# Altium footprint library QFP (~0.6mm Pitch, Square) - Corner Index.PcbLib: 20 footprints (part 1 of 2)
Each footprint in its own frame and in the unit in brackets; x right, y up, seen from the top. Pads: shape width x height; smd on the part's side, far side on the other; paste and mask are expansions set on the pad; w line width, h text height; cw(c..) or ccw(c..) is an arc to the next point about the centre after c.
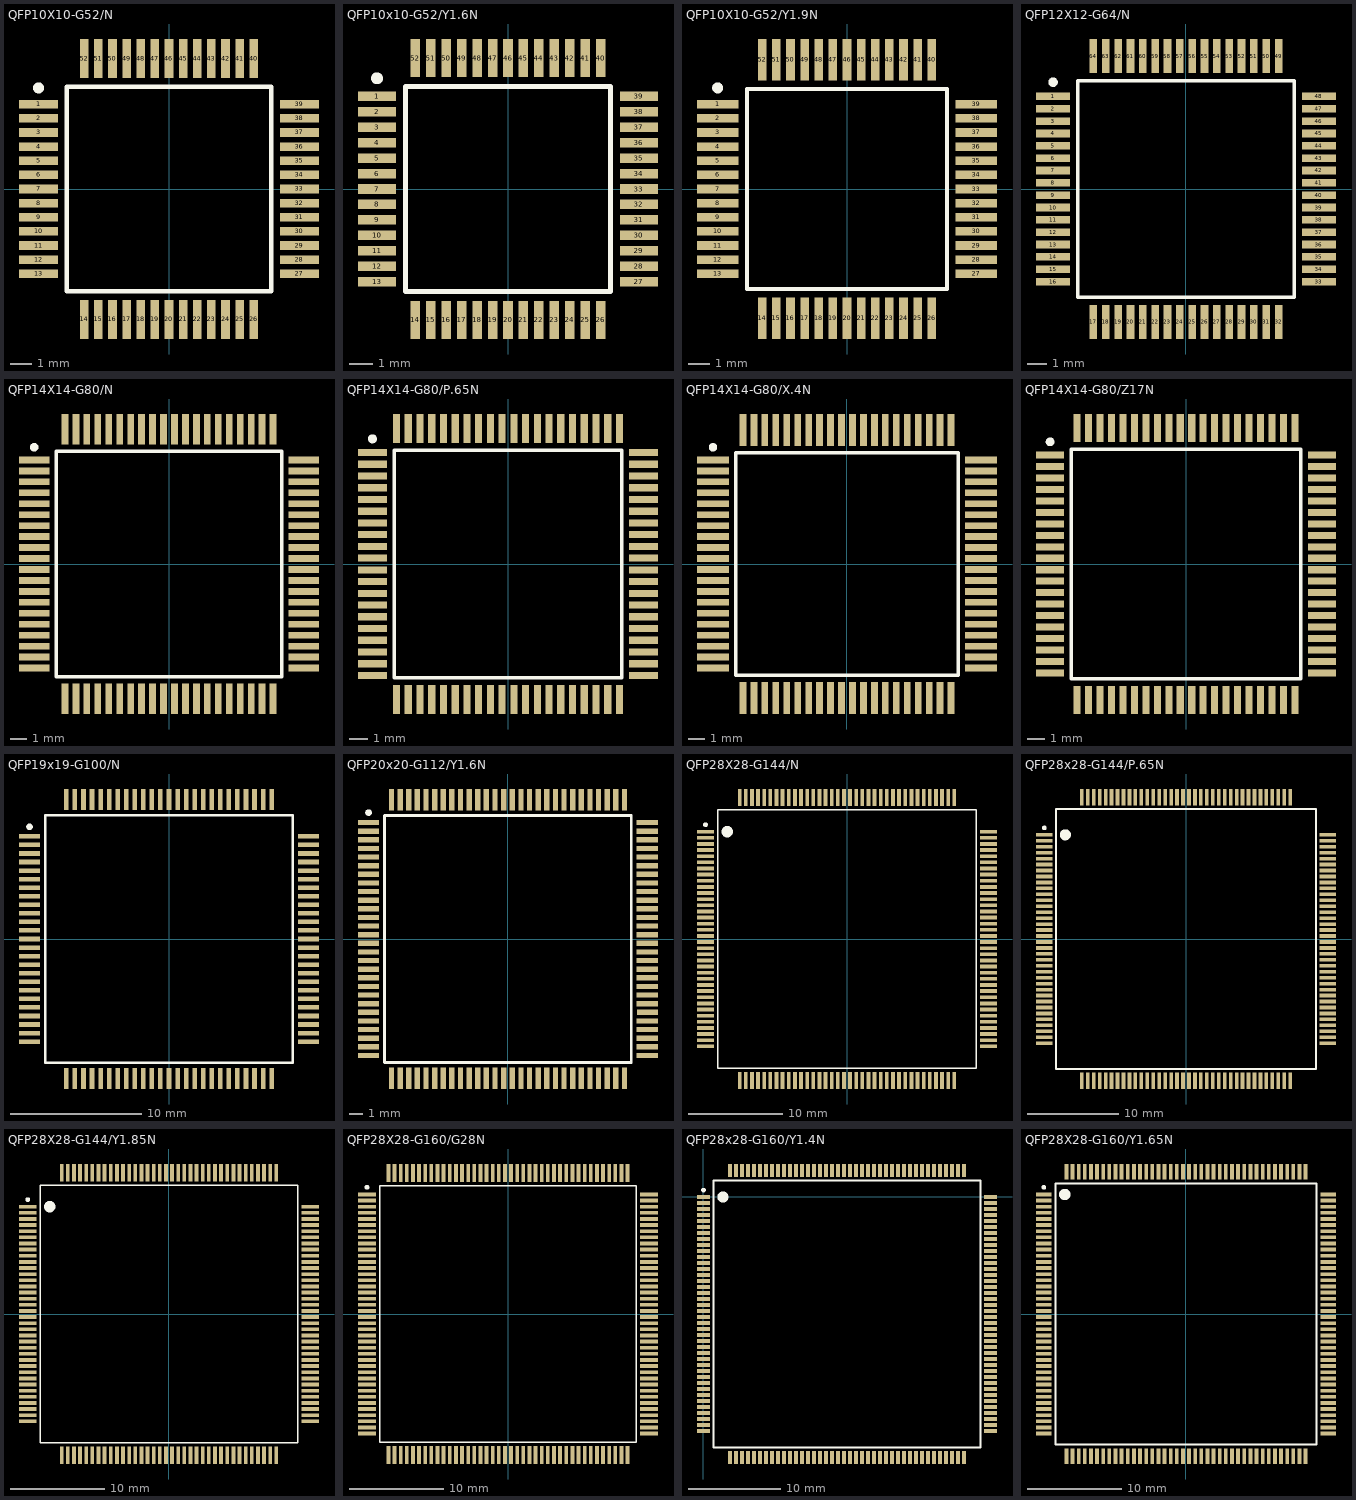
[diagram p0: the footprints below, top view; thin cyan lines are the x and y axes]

## QFP10X10-G52/N [mm]
pads (52):
  rect 1.8x0.4 smd: 1(-6,3.9) 2(-6,3.25) 3(-6,2.6) 4(-6,1.95) 5(-6,1.3) 6(-6,0.65) 7(-6,0) 8(-6,-0.65) 9(-6,-1.3) 10(-6,-1.95) 11(-6,-2.6) 12(-6,-3.25) 13(-6,-3.9) 27(6,-3.9) 28(6,-3.25) 29(6,-2.6) 30(6,-1.95) 31(6,-1.3) 32(6,-0.65) 33(6,0) 34(6,0.65) 35(6,1.3) 36(6,1.95) 37(6,2.6) 38(6,3.25) 39(6,3.9)
  rect 0.4x1.8 smd: 14(-3.9,-6) 15(-3.25,-6) 16(-2.6,-6) 17(-1.95,-6) 18(-1.3,-6) 19(-0.65,-6) 20(0,-6) 21(0.65,-6) 22(1.3,-6) 23(1.95,-6) 24(2.6,-6) 25(3.25,-6) 26(3.9,-6) 40(3.9,6) 41(3.25,6) 42(2.6,6) 43(1.95,6) 44(1.3,6) 45(0.65,6) 46(0,6) 47(-0.65,6) 48(-1.3,6) 49(-1.95,6) 50(-2.6,6) 51(-3.25,6) 52(-3.9,6)
Top Overlay:
  circle w0.25: c-6,4.65 r0.125
  lines w0.2: -4.7,-4.7 4.7,-4.7 4.7,4.7 -4.7,4.7 -4.7,-4.7

## QFP10x10-G52/Y1.6N [mm]
pads (52):
  rect 1.6x0.4 smd: 1(-5.5,3.9) 2(-5.5,3.25) 3(-5.5,2.6) 4(-5.5,1.95) 5(-5.5,1.3) 6(-5.5,0.65) 7(-5.5,0) 8(-5.5,-0.65) 9(-5.5,-1.3) 10(-5.5,-1.95) 11(-5.5,-2.6) 12(-5.5,-3.25) 13(-5.5,-3.9) 27(5.5,-3.9) 28(5.5,-3.25) 29(5.5,-2.6) 30(5.5,-1.95) 31(5.5,-1.3) 32(5.5,-0.65) 33(5.5,0) 34(5.5,0.65) 35(5.5,1.3) 36(5.5,1.95) 37(5.5,2.6) 38(5.5,3.25) 39(5.5,3.9)
  rect 0.4x1.6 smd: 14(-3.9,-5.5) 15(-3.25,-5.5) 16(-2.6,-5.5) 17(-1.95,-5.5) 18(-1.3,-5.5) 19(-0.65,-5.5) 20(0,-5.5) 21(0.65,-5.5) 22(1.3,-5.5) 23(1.95,-5.5) 24(2.6,-5.5) 25(3.25,-5.5) 26(3.9,-5.5) 40(3.9,5.5) 41(3.25,5.5) 42(2.6,5.5) 43(1.95,5.5) 44(1.3,5.5) 45(0.65,5.5) 46(0,5.5) 47(-0.65,5.5) 48(-1.3,5.5) 49(-1.95,5.5) 50(-2.6,5.5) 51(-3.25,5.5) 52(-3.9,5.5)
Top Overlay:
  circle w0.25: c-5.5,4.65 r0.125
  lines w0.2: -4.3,-4.3 -4.3,4.3 4.3,4.3 4.3,-4.3 -4.3,-4.3

## QFP10X10-G52/Y1.9N [mm]
pads (52):
  rect 1.9x0.4 smd: 1(-5.95,3.9) 2(-5.95,3.25) 3(-5.95,2.6) 4(-5.95,1.95) 5(-5.95,1.3) 6(-5.95,0.65) 7(-5.95,0) 8(-5.95,-0.65) 9(-5.95,-1.3) 10(-5.95,-1.95) 11(-5.95,-2.6) 12(-5.95,-3.25) 13(-5.95,-3.9) 27(5.95,-3.9) 28(5.95,-3.25) 29(5.95,-2.6) 30(5.95,-1.95) 31(5.95,-1.3) 32(5.95,-0.65) 33(5.95,0) 34(5.95,0.65) 35(5.95,1.3) 36(5.95,1.95) 37(5.95,2.6) 38(5.95,3.25) 39(5.95,3.9)
  rect 0.4x1.9 smd: 14(-3.9,-5.95) 15(-3.25,-5.95) 16(-2.6,-5.95) 17(-1.95,-5.95) 18(-1.3,-5.95) 19(-0.65,-5.95) 20(0,-5.95) 21(0.65,-5.95) 22(1.3,-5.95) 23(1.95,-5.95) 24(2.6,-5.95) 25(3.25,-5.95) 26(3.9,-5.95) 40(3.9,5.95) 41(3.25,5.95) 42(2.6,5.95) 43(1.95,5.95) 44(1.3,5.95) 45(0.65,5.95) 46(0,5.95) 47(-0.65,5.95) 48(-1.3,5.95) 49(-1.95,5.95) 50(-2.6,5.95) 51(-3.25,5.95) 52(-3.9,5.95)
Top Overlay:
  circle w0.25: c-5.95,4.65 r0.125
  lines w0.2: -4.6,-4.6 4.6,-4.6 4.6,4.6 -4.6,4.6 -4.6,-4.6

## QFP12X12-G64/N [mm]
pads (64):
  rect 1.8x0.4 smd: 1(-7,4.875) 2(-7,4.225) 3(-7,3.575) 4(-7,2.925) 5(-7,2.275) 6(-7,1.625) 7(-7,0.975) 8(-7,0.325) 9(-7,-0.325) 10(-7,-0.975) 11(-7,-1.625) 12(-7,-2.275) 13(-7,-2.925) 14(-7,-3.575) 15(-7,-4.225) 16(-7,-4.875) 33(7,-4.875) 34(7,-4.225) 35(7,-3.575) 36(7,-2.925) 37(7,-2.275) 38(7,-1.625) 39(7,-0.975) 40(7,-0.325) 41(7,0.325) 42(7,0.975) 43(7,1.625) 44(7,2.275) 45(7,2.925) 46(7,3.575) 47(7,4.225) 48(7,4.875)
  rect 0.4x1.8 smd: 17(-4.875,-7) 18(-4.225,-7) 19(-3.575,-7) 20(-2.925,-7) 21(-2.275,-7) 22(-1.625,-7) 23(-0.975,-7) 24(-0.325,-7) 25(0.325,-7) 26(0.975,-7) 27(1.625,-7) 28(2.275,-7) 29(2.925,-7) 30(3.575,-7) 31(4.225,-7) 32(4.875,-7) 49(4.875,7) 50(4.225,7) 51(3.575,7) 52(2.925,7) 53(2.275,7) 54(1.625,7) 55(0.975,7) 56(0.325,7) 57(-0.325,7) 58(-0.975,7) 59(-1.625,7) 60(-2.275,7) 61(-2.925,7) 62(-3.575,7) 63(-4.225,7) 64(-4.875,7)
Top Overlay:
  circle w0.25: c-7,5.625 r0.125
  lines w0.2: -5.7,-5.7 -5.7,5.7 5.7,5.7 5.7,-5.7 -5.7,-5.7

## QFP14X14-G80/N [mm]
pads (80):
  rect 1.8x0.4 smd: 1(-8,6.175) 2(-8,5.525) 3(-8,4.875) 4(-8,4.225) 5(-8,3.575) 6(-8,2.925) 7(-8,2.275) 8(-8,1.625) 9(-8,0.975) 10(-8,0.325) 11(-8,-0.325) 12(-8,-0.975) 13(-8,-1.625) 14(-8,-2.275) 15(-8,-2.925) 16(-8,-3.575) 17(-8,-4.225) 18(-8,-4.875) 19(-8,-5.525) 20(-8,-6.175) 41(8,-6.175) 42(8,-5.525) 43(8,-4.875) 44(8,-4.225) 45(8,-3.575) 46(8,-2.925) 47(8,-2.275) 48(8,-1.625) 49(8,-0.975) 50(8,-0.325) 51(8,0.325) 52(8,0.975) 53(8,1.625) 54(8,2.275) 55(8,2.925) 56(8,3.575) 57(8,4.225) 58(8,4.875) 59(8,5.525) 60(8,6.175)
  rect 0.4x1.8 smd: 21(-6.175,-8) 22(-5.525,-8) 23(-4.875,-8) 24(-4.225,-8) 25(-3.575,-8) 26(-2.925,-8) 27(-2.275,-8) 28(-1.625,-8) 29(-0.975,-8) 30(-0.325,-8) 31(0.325,-8) 32(0.975,-8) 33(1.625,-8) 34(2.275,-8) 35(2.925,-8) 36(3.575,-8) 37(4.225,-8) 38(4.875,-8) 39(5.525,-8) 40(6.175,-8) 61(6.175,8) 62(5.525,8) 63(4.875,8) 64(4.225,8) 65(3.575,8) 66(2.925,8) 67(2.275,8) 68(1.625,8) 69(0.975,8) 70(0.325,8) 71(-0.325,8) 72(-0.975,8) 73(-1.625,8) 74(-2.275,8) 75(-2.925,8) 76(-3.575,8) 77(-4.225,8) 78(-4.875,8) 79(-5.525,8) 80(-6.175,8)
Top Overlay:
  circle w0.25: c-8,6.925 r0.125
  lines w0.2: -6.7,-6.7 -6.7,6.7 6.7,6.7 6.7,-6.7 -6.7,-6.7

## QFP14X14-G80/P.65N [mm]
pads (80):
  rect 1.6x0.4 smd: 1(-7.5,6.175) 2(-7.5,5.525) 3(-7.5,4.875) 4(-7.5,4.225) 5(-7.5,3.575) 6(-7.5,2.925) 7(-7.5,2.275) 8(-7.5,1.625) 9(-7.5,0.975) 10(-7.5,0.325) 11(-7.5,-0.325) 12(-7.5,-0.975) 13(-7.5,-1.625) 14(-7.5,-2.275) 15(-7.5,-2.925) 16(-7.5,-3.575) 17(-7.5,-4.225) 18(-7.5,-4.875) 19(-7.5,-5.525) 20(-7.5,-6.175) 41(7.5,-6.175) 42(7.5,-5.525) 43(7.5,-4.875) 44(7.5,-4.225) 45(7.5,-3.575) 46(7.5,-2.925) 47(7.5,-2.275) 48(7.5,-1.625) 49(7.5,-0.975) 50(7.5,-0.325) 51(7.5,0.325) 52(7.5,0.975) 53(7.5,1.625) 54(7.5,2.275) 55(7.5,2.925) 56(7.5,3.575) 57(7.5,4.225) 58(7.5,4.875) 59(7.5,5.525) 60(7.5,6.175)
  rect 0.4x1.6 smd: 21(-6.175,-7.5) 22(-5.525,-7.5) 23(-4.875,-7.5) 24(-4.225,-7.5) 25(-3.575,-7.5) 26(-2.925,-7.5) 27(-2.275,-7.5) 28(-1.625,-7.5) 29(-0.975,-7.5) 30(-0.325,-7.5) 31(0.325,-7.5) 32(0.975,-7.5) 33(1.625,-7.5) 34(2.275,-7.5) 35(2.925,-7.5) 36(3.575,-7.5) 37(4.225,-7.5) 38(4.875,-7.5) 39(5.525,-7.5) 40(6.175,-7.5) 61(6.175,7.5) 62(5.525,7.5) 63(4.875,7.5) 64(4.225,7.5) 65(3.575,7.5) 66(2.925,7.5) 67(2.275,7.5) 68(1.625,7.5) 69(0.975,7.5) 70(0.325,7.5) 71(-0.325,7.5) 72(-0.975,7.5) 73(-1.625,7.5) 74(-2.275,7.5) 75(-2.925,7.5) 76(-3.575,7.5) 77(-4.225,7.5) 78(-4.875,7.5) 79(-5.525,7.5) 80(-6.175,7.5)
Top Overlay:
  circle w0.25: c-7.5,6.925 r0.125
  lines w0.2: -6.3,-6.3 6.3,-6.3 6.3,6.3 -6.3,6.3 -6.3,-6.3

## QFP14X14-G80/X.4N [mm]
pads (80):
  rect 1.9x0.4 smd: 1(-7.95,6.175) 2(-7.95,5.525) 3(-7.95,4.875) 4(-7.95,4.225) 5(-7.95,3.575) 6(-7.95,2.925) 7(-7.95,2.275) 8(-7.95,1.625) 9(-7.95,0.975) 10(-7.95,0.325) 11(-7.95,-0.325) 12(-7.95,-0.975) 13(-7.95,-1.625) 14(-7.95,-2.275) 15(-7.95,-2.925) 16(-7.95,-3.575) 17(-7.95,-4.225) 18(-7.95,-4.875) 19(-7.95,-5.525) 20(-7.95,-6.175) 41(7.95,-6.175) 42(7.95,-5.525) 43(7.95,-4.875) 44(7.95,-4.225) 45(7.95,-3.575) 46(7.95,-2.925) 47(7.95,-2.275) 48(7.95,-1.625) 49(7.95,-0.975) 50(7.95,-0.325) 51(7.95,0.325) 52(7.95,0.975) 53(7.95,1.625) 54(7.95,2.275) 55(7.95,2.925) 56(7.95,3.575) 57(7.95,4.225) 58(7.95,4.875) 59(7.95,5.525) 60(7.95,6.175)
  rect 0.4x1.9 smd: 21(-6.175,-7.95) 22(-5.525,-7.95) 23(-4.875,-7.95) 24(-4.225,-7.95) 25(-3.575,-7.95) 26(-2.925,-7.95) 27(-2.275,-7.95) 28(-1.625,-7.95) 29(-0.975,-7.95) 30(-0.325,-7.95) 31(0.325,-7.95) 32(0.975,-7.95) 33(1.625,-7.95) 34(2.275,-7.95) 35(2.925,-7.95) 36(3.575,-7.95) 37(4.225,-7.95) 38(4.875,-7.95) 39(5.525,-7.95) 40(6.175,-7.95) 61(6.175,7.95) 62(5.525,7.95) 63(4.875,7.95) 64(4.225,7.95) 65(3.575,7.95) 66(2.925,7.95) 67(2.275,7.95) 68(1.625,7.95) 69(0.975,7.95) 70(0.325,7.95) 71(-0.325,7.95) 72(-0.975,7.95) 73(-1.625,7.95) 74(-2.275,7.95) 75(-2.925,7.95) 76(-3.575,7.95) 77(-4.225,7.95) 78(-4.875,7.95) 79(-5.525,7.95) 80(-6.175,7.95)
Top Overlay:
  circle w0.25: c-7.95,6.925 r0.125
  lines w0.2: -6.6,-6.6 6.6,-6.6 6.6,6.6 -6.6,6.6 -6.6,-6.6

## QFP14X14-G80/Z17N [mm]
pads (80):
  rect 1.6x0.4 smd: 1(-7.7,6.175) 2(-7.7,5.525) 3(-7.7,4.875) 4(-7.7,4.225) 5(-7.7,3.575) 6(-7.7,2.925) 7(-7.7,2.275) 8(-7.7,1.625) 9(-7.7,0.975) 10(-7.7,0.325) 11(-7.7,-0.325) 12(-7.7,-0.975) 13(-7.7,-1.625) 14(-7.7,-2.275) 15(-7.7,-2.925) 16(-7.7,-3.575) 17(-7.7,-4.225) 18(-7.7,-4.875) 19(-7.7,-5.525) 20(-7.7,-6.175) 41(7.7,-6.175) 42(7.7,-5.525) 43(7.7,-4.875) 44(7.7,-4.225) 45(7.7,-3.575) 46(7.7,-2.925) 47(7.7,-2.275) 48(7.7,-1.625) 49(7.7,-0.975) 50(7.7,-0.325) 51(7.7,0.325) 52(7.7,0.975) 53(7.7,1.625) 54(7.7,2.275) 55(7.7,2.925) 56(7.7,3.575) 57(7.7,4.225) 58(7.7,4.875) 59(7.7,5.525) 60(7.7,6.175)
  rect 0.4x1.6 smd: 21(-6.175,-7.7) 22(-5.525,-7.7) 23(-4.875,-7.7) 24(-4.225,-7.7) 25(-3.575,-7.7) 26(-2.925,-7.7) 27(-2.275,-7.7) 28(-1.625,-7.7) 29(-0.975,-7.7) 30(-0.325,-7.7) 31(0.325,-7.7) 32(0.975,-7.7) 33(1.625,-7.7) 34(2.275,-7.7) 35(2.925,-7.7) 36(3.575,-7.7) 37(4.225,-7.7) 38(4.875,-7.7) 39(5.525,-7.7) 40(6.175,-7.7) 61(6.175,7.7) 62(5.525,7.7) 63(4.875,7.7) 64(4.225,7.7) 65(3.575,7.7) 66(2.925,7.7) 67(2.275,7.7) 68(1.625,7.7) 69(0.975,7.7) 70(0.325,7.7) 71(-0.325,7.7) 72(-0.975,7.7) 73(-1.625,7.7) 74(-2.275,7.7) 75(-2.925,7.7) 76(-3.575,7.7) 77(-4.225,7.7) 78(-4.875,7.7) 79(-5.525,7.7) 80(-6.175,7.7)
Top Overlay:
  circle w0.25: c-7.7,6.925 r0.125
  lines w0.2: -6.5,-6.5 6.5,-6.5 6.5,6.5 -6.5,6.5 -6.5,-6.5

## QFP19x19-G100/N [mm]
pads (100):
  rect 1.6x0.35 smd: 1(-10.6,7.8) 2(-10.6,7.15) 3(-10.6,6.5) 4(-10.6,5.85) 5(-10.6,5.2) 6(-10.6,4.55) 7(-10.6,3.9) 8(-10.6,3.25) 9(-10.6,2.6) 10(-10.6,1.95) 11(-10.6,1.3) 12(-10.6,0.65) 13(-10.6,0) 14(-10.6,-0.65) 15(-10.6,-1.3) 16(-10.6,-1.95) 17(-10.6,-2.6) 18(-10.6,-3.25) 19(-10.6,-3.9) 20(-10.6,-4.55) 21(-10.6,-5.2) 22(-10.6,-5.85) 23(-10.6,-6.5) 24(-10.6,-7.15) 25(-10.6,-7.8) 51(10.6,-7.8) 52(10.6,-7.15) 53(10.6,-6.5) 54(10.6,-5.85) 55(10.6,-5.2) 56(10.6,-4.55) 57(10.6,-3.9) 58(10.6,-3.25) 59(10.6,-2.6) 60(10.6,-1.95) 61(10.6,-1.3) 62(10.6,-0.65) 63(10.6,0) 64(10.6,0.65) 65(10.6,1.3) 66(10.6,1.95) 67(10.6,2.6) 68(10.6,3.25) 69(10.6,3.9) 70(10.6,4.55) 71(10.6,5.2) 72(10.6,5.85) 73(10.6,6.5) 74(10.6,7.15) 75(10.6,7.8)
  rect 0.35x1.6 smd: 26(-7.8,-10.6) 27(-7.15,-10.6) 28(-6.5,-10.6) 29(-5.85,-10.6) 30(-5.2,-10.6) 31(-4.55,-10.6) 32(-3.9,-10.6) 33(-3.25,-10.6) 34(-2.6,-10.6) 35(-1.95,-10.6) 36(-1.3,-10.6) 37(-0.65,-10.6) 38(0,-10.6) 39(0.65,-10.6) 40(1.3,-10.6) 41(1.95,-10.6) 42(2.6,-10.6) 43(3.25,-10.6) 44(3.9,-10.6) 45(4.55,-10.6) 46(5.2,-10.6) 47(5.85,-10.6) 48(6.5,-10.6) 49(7.15,-10.6) 50(7.8,-10.6) 76(7.8,10.6) 77(7.15,10.6) 78(6.5,10.6) 79(5.85,10.6) 80(5.2,10.6) 81(4.55,10.6) 82(3.9,10.6) 83(3.25,10.6) 84(2.6,10.6) 85(1.95,10.6) 86(1.3,10.6) 87(0.65,10.6) 88(0,10.6) 89(-0.65,10.6) 90(-1.3,10.6) 91(-1.95,10.6) 92(-2.6,10.6) 93(-3.25,10.6) 94(-3.9,10.6) 95(-4.55,10.6) 96(-5.2,10.6) 97(-5.85,10.6) 98(-6.5,10.6) 99(-7.15,10.6) 100(-7.8,10.6)
Top Overlay:
  circle w0.25: c-10.6,8.525 r0.125
  lines w0.2: -9.4,-9.4 -9.4,9.4 9.4,9.4 9.4,-9.4 -9.4,-9.4

## QFP20x20-G112/Y1.6N [mm]
pads (112):
  rect 1.6x0.4 smd: 1(-10.5,8.775) 2(-10.5,8.125) 3(-10.5,7.475) 4(-10.5,6.825) 5(-10.5,6.175) 6(-10.5,5.525) 7(-10.5,4.875) 8(-10.5,4.225) 9(-10.5,3.575) 10(-10.5,2.925) 11(-10.5,2.275) 12(-10.5,1.625) 13(-10.5,0.975) 14(-10.5,0.325) 15(-10.5,-0.325) 16(-10.5,-0.975) 17(-10.5,-1.625) 18(-10.5,-2.275) 19(-10.5,-2.925) 20(-10.5,-3.575) 21(-10.5,-4.225) 22(-10.5,-4.875) 23(-10.5,-5.525) 24(-10.5,-6.175) 25(-10.5,-6.825) 26(-10.5,-7.475) 27(-10.5,-8.125) 28(-10.5,-8.775) 57(10.5,-8.775) 58(10.5,-8.125) 59(10.5,-7.475) 60(10.5,-6.825) 61(10.5,-6.175) 62(10.505,-5.525) 63(10.5,-4.875) 64(10.5,-4.225) 65(10.5,-3.575) 66(10.5,-2.925) 67(10.5,-2.275) 68(10.5,-1.625) 69(10.5,-0.975) 70(10.5,-0.325) 71(10.5,0.325) 72(10.5,0.975) 73(10.5,1.625) 74(10.5,2.275) 75(10.5,2.925) 76(10.5,3.575) 77(10.5,4.225) 78(10.5,4.875) 79(10.5,5.525) 80(10.5,6.175) 81(10.5,6.825) 82(10.5,7.475) 83(10.5,8.125) 84(10.5,8.775)
  rect 0.4x1.6 smd: 29(-8.775,-10.5) 30(-8.125,-10.5) 31(-7.475,-10.5) 32(-6.825,-10.5) 33(-6.175,-10.5) 34(-5.525,-10.5) 35(-4.875,-10.5) 36(-4.225,-10.5) 37(-3.575,-10.5) 38(-2.925,-10.5) 39(-2.275,-10.5) 40(-1.625,-10.5) 41(-0.975,-10.5) 42(-0.325,-10.5) 43(0.325,-10.5) 44(0.975,-10.5) 45(1.625,-10.5) 46(2.275,-10.5) 47(2.925,-10.5) 48(3.575,-10.5) 49(4.225,-10.5) 50(4.875,-10.5) 51(5.525,-10.5) 52(6.175,-10.5) 53(6.825,-10.5) 54(7.475,-10.5) 55(8.125,-10.5) 56(8.775,-10.5) 85(8.775,10.5) 86(8.125,10.5) 87(7.475,10.5) 88(6.825,10.5) 89(6.175,10.5) 90(5.525,10.5) 91(4.875,10.5) 92(4.225,10.5) 93(3.575,10.5) 94(2.925,10.5) 95(2.275,10.5) 96(1.625,10.5) 97(0.975,10.5) 98(0.325,10.5) 99(-0.325,10.5) 100(-0.975,10.5) 101(-1.625,10.5) 102(-2.275,10.5) 103(-2.925,10.5) 104(-3.575,10.5) 105(-4.225,10.5) 106(-4.875,10.5) 107(-5.525,10.5) 108(-6.175,10.5) 109(-6.825,10.5) 110(-7.475,10.5) 111(-8.125,10.5) 112(-8.775,10.5)
Top Overlay:
  circle w0.25: c-10.505,9.525 r0.125
  lines w0.2: -9.3,-9.3 9.3,-9.3 9.3,9.3 -9.3,9.3 -9.3,-9.3

## QFP28X28-G144/N [mm]
pads (144):
  rect 1.8x0.4 smd: 1(-15,11.375) 2(-15,10.725) 3(-15,10.075) 4(-15,9.425) 5(-15,8.775) 6(-15,8.125) 7(-15,7.475) 8(-15,6.825) 9(-15,6.175) 10(-15,5.525) 11(-15,4.875) 12(-15,4.225) 13(-15,3.575) 14(-15,2.925) 15(-15,2.275) 16(-15,1.625) 17(-15,0.975) 18(-15,0.325) 19(-15,-0.325) 20(-15,-0.975) 21(-15,-1.625) 22(-15,-2.275) 23(-15,-2.925) 24(-15,-3.575) 25(-15,-4.225) 26(-15,-4.875) 27(-15,-5.525) 28(-15,-6.175) 29(-15,-6.825) 30(-15,-7.475) 31(-15,-8.125) 32(-15,-8.775) 33(-15,-9.425) 34(-15,-10.075) 35(-15,-10.725) 36(-15,-11.375) 73(15,-11.375) 74(15,-10.725) 75(15,-10.075) 76(15,-9.425) 77(15,-8.775) 78(15,-8.125) 79(15,-7.475) 80(15,-6.825) 81(15,-6.175) 82(15,-5.525) 83(15,-4.875) 84(15,-4.225) 85(15,-3.575) 86(15,-2.925) 87(15,-2.275) 88(15,-1.625) 89(15,-0.975) 90(15,-0.325) 91(15,0.325) 92(15,0.975) 93(15,1.625) 94(15,2.275) 95(15,2.925) 96(15,3.575) 97(15,4.225) 98(15,4.875) 99(15,5.525) 100(15,6.175) 101(15,6.825) 102(15,7.475) 103(15,8.125) 104(15,8.775) 105(15,9.425) 106(15,10.075) 107(15,10.725) 108(15,11.375)
  rect 0.4x1.8 smd: 37(-11.375,-15) 38(-10.725,-15) 39(-10.075,-15) 40(-9.425,-15) 41(-8.775,-15) 42(-8.125,-15) 43(-7.475,-15) 44(-6.825,-15) 45(-6.175,-15) 46(-5.525,-15) 47(-4.875,-15) 48(-4.225,-15) 49(-3.575,-15) 50(-2.925,-15) 51(-2.275,-15) 52(-1.625,-15) 53(-0.975,-15) 54(-0.325,-15) 55(0.325,-15) 56(0.975,-15) 57(1.625,-15) 58(2.275,-15) 59(2.925,-15) 60(3.575,-15) 61(4.225,-15) 62(4.875,-15) 63(5.525,-15) 64(6.175,-15) 65(6.825,-15) 66(7.475,-15) 67(8.125,-15) 68(8.775,-15) 69(9.425,-15) 70(10.075,-15) 71(10.725,-15) 72(11.375,-15) 109(11.375,15) 110(10.725,15) 111(10.075,15) 112(9.425,15) 113(8.775,15) 114(8.125,15) 115(7.475,15) 116(6.825,15) 117(6.175,15) 118(5.525,15) 119(4.875,15) 120(4.225,15) 121(3.575,15) 122(2.925,15) 123(2.275,15) 124(1.625,15) 125(0.975,15) 126(0.325,15) 127(-0.325,15) 128(-0.975,15) 129(-1.625,15) 130(-2.275,15) 131(-2.925,15) 132(-3.575,15) 133(-4.225,15) 134(-4.875,15) 135(-5.525,15) 136(-6.175,15) 137(-6.825,15) 138(-7.475,15) 139(-8.125,15) 140(-8.775,15) 141(-9.425,15) 142(-10.075,15) 143(-10.725,15) 144(-11.375,15)
Top Overlay:
  circle w0.25: c-15,12.125 r0.125
  circle w0.6: c-12.7,11.375 r0.3
  lines w0.2: -13.7,-13.7 -13.7,13.7 13.7,13.7 13.7,-13.7 -13.7,-13.7

## QFP28x28-G144/P.65N [mm]
pads (144):
  rect 1.8x0.4 smd: 1(-15.475,11.375) 2(-15.475,10.725) 3(-15.475,10.075) 4(-15.475,9.425) 5(-15.475,8.775) 6(-15.475,8.125) 7(-15.475,7.475) 8(-15.475,6.825) 9(-15.475,6.175) 10(-15.475,5.525) 11(-15.475,4.875) 12(-15.475,4.225) 13(-15.475,3.575) 14(-15.475,2.925) 15(-15.475,2.275) 16(-15.475,1.625) 17(-15.475,0.975) 18(-15.475,0.325) 19(-15.475,-0.325) 20(-15.475,-0.975) 21(-15.475,-1.625) 22(-15.475,-2.275) 23(-15.475,-2.925) 24(-15.475,-3.575) 25(-15.475,-4.225) 26(-15.475,-4.875) 27(-15.475,-5.525) 28(-15.475,-6.175) 29(-15.475,-6.825) 30(-15.475,-7.475) 31(-15.475,-8.125) 32(-15.475,-8.775) 33(-15.475,-9.425) 34(-15.475,-10.075) 35(-15.475,-10.725) 36(-15.475,-11.375) 73(15.475,-11.375) 74(15.475,-10.725) 75(15.475,-10.075) 76(15.475,-9.425) 77(15.475,-8.775) 78(15.475,-8.125) 79(15.475,-7.475) 80(15.475,-6.825) 81(15.475,-6.175) 82(15.475,-5.525) 83(15.475,-4.875) 84(15.475,-4.225) 85(15.475,-3.575) 86(15.475,-2.925) 87(15.475,-2.275) 88(15.475,-1.625) 89(15.475,-0.975) 90(15.475,-0.325) 91(15.475,0.325) 92(15.475,0.975) 93(15.475,1.625) 94(15.475,2.275) 95(15.475,2.925) 96(15.475,3.575) 97(15.475,4.225) 98(15.475,4.875) 99(15.475,5.525) 100(15.475,6.175) 101(15.475,6.825) 102(15.475,7.475) 103(15.475,8.125) 104(15.475,8.775) 105(15.475,9.425) 106(15.475,10.075) 107(15.475,10.725) 108(15.475,11.375)
  rect 0.4x1.8 smd: 37(-11.375,-15.475) 38(-10.725,-15.475) 39(-10.075,-15.475) 40(-9.425,-15.475) 41(-8.775,-15.475) 42(-8.125,-15.475) 43(-7.475,-15.475) 44(-6.825,-15.475) 45(-6.175,-15.475) 46(-5.525,-15.475) 47(-4.875,-15.475) 48(-4.225,-15.475) 49(-3.575,-15.475) 50(-2.925,-15.475) 51(-2.275,-15.475) 52(-1.625,-15.475) 53(-0.975,-15.475) 54(-0.325,-15.475) 55(0.325,-15.475) 56(0.975,-15.475) 57(1.625,-15.475) 58(2.275,-15.475) 59(2.925,-15.475) 60(3.575,-15.475) 61(4.225,-15.475) 62(4.875,-15.475) 63(5.525,-15.475) 64(6.175,-15.475) 65(6.825,-15.475) 66(7.475,-15.475) 67(8.125,-15.475) 68(8.775,-15.475) 69(9.425,-15.475) 70(10.075,-15.475) 71(10.725,-15.475) 72(11.375,-15.475) 109(11.375,15.475) 110(10.725,15.475) 111(10.075,15.475) 112(9.425,15.475) 113(8.775,15.475) 114(8.125,15.475) 115(7.475,15.475) 116(6.825,15.475) 117(6.175,15.475) 118(5.525,15.475) 119(4.875,15.475) 120(4.225,15.475) 121(3.575,15.475) 122(2.925,15.475) 123(2.275,15.475) 124(1.625,15.475) 125(0.975,15.475) 126(0.325,15.475) 127(-0.325,15.475) 128(-0.975,15.475) 129(-1.625,15.475) 130(-2.275,15.475) 131(-2.925,15.475) 132(-3.575,15.475) 133(-4.225,15.475) 134(-4.875,15.475) 135(-5.525,15.475) 136(-6.175,15.475) 137(-6.825,15.475) 138(-7.475,15.475) 139(-8.125,15.475) 140(-8.775,15.475) 141(-9.425,15.475) 142(-10.075,15.475) 143(-10.725,15.475) 144(-11.375,15.475)
Top Overlay:
  circle w0.25: c-15.475,12.125 r0.125
  circle w0.6: c-13.175,11.375 r0.3
  lines w0.2: -14.175,-14.175 -14.175,14.175 14.175,14.175 14.175,-14.175 -14.175,-14.175

## QFP28X28-G144/Y1.85N [mm]
pads (144):
  rect 1.85x0.4 smd: 1(-14.975,11.375) 2(-14.975,10.725) 3(-14.975,10.075) 4(-14.975,9.425) 5(-14.975,8.775) 6(-14.975,8.125) 7(-14.975,7.475) 8(-14.975,6.825) 9(-14.975,6.175) 10(-14.975,5.525) 11(-14.975,4.875) 12(-14.975,4.225) 13(-14.975,3.575) 14(-14.975,2.925) 15(-14.975,2.275) 16(-14.975,1.625) 17(-14.975,0.975) 18(-14.975,0.325) 19(-14.975,-0.325) 20(-14.975,-0.975) 21(-14.975,-1.625) 22(-14.975,-2.275) 23(-14.975,-2.925) 24(-14.975,-3.575) 25(-14.975,-4.225) 26(-14.975,-4.875) 27(-14.975,-5.525) 28(-14.975,-6.175) 29(-14.975,-6.825) 30(-14.975,-7.475) 31(-14.975,-8.125) 32(-14.975,-8.775) 33(-14.975,-9.425) 34(-14.975,-10.075) 35(-14.975,-10.725) 36(-14.975,-11.375) 73(14.975,-11.375) 74(14.975,-10.725) 75(14.975,-10.075) 76(14.975,-9.425) 77(14.975,-8.775) 78(14.975,-8.125) 79(14.975,-7.475) 80(14.975,-6.825) 81(14.975,-6.175) 82(14.975,-5.525) 83(14.975,-4.875) 84(14.975,-4.225) 85(14.975,-3.575) 86(14.975,-2.925) 87(14.975,-2.275) 88(14.975,-1.625) 89(14.975,-0.975) 90(14.975,-0.325) 91(14.975,0.325) 92(14.975,0.975) 93(14.975,1.625) 94(14.975,2.275) 95(14.975,2.925) 96(14.975,3.575) 97(14.975,4.225) 98(14.975,4.875) 99(14.975,5.525) 100(14.975,6.175) 101(14.975,6.825) 102(14.975,7.475) 103(14.975,8.125) 104(14.975,8.775) 105(14.975,9.425) 106(14.975,10.075) 107(14.975,10.725) 108(14.975,11.375)
  rect 0.4x1.85 smd: 37(-11.375,-14.975) 38(-10.725,-14.975) 39(-10.075,-14.975) 40(-9.425,-14.975) 41(-8.775,-14.975) 42(-8.125,-14.975) 43(-7.475,-14.975) 44(-6.825,-14.975) 45(-6.175,-14.975) 46(-5.525,-14.975) 47(-4.875,-14.975) 48(-4.225,-14.975) 49(-3.575,-14.975) 50(-2.925,-14.975) 51(-2.275,-14.975) 52(-1.625,-14.975) 53(-0.975,-14.975) 54(-0.325,-14.975) 55(0.325,-14.975) 56(0.975,-14.975) 57(1.625,-14.975) 58(2.275,-14.975) 59(2.925,-14.975) 60(3.575,-14.975) 61(4.225,-14.975) 62(4.875,-14.975) 63(5.525,-14.975) 64(6.175,-14.975) 65(6.825,-14.975) 66(7.475,-14.975) 67(8.125,-14.975) 68(8.775,-14.975) 69(9.425,-14.975) 70(10.075,-14.975) 71(10.725,-14.975) 72(11.375,-14.975) 109(11.375,14.975) 110(10.725,14.975) 111(10.075,14.975) 112(9.425,14.975) 113(8.775,14.975) 114(8.125,14.975) 115(7.475,14.975) 116(6.825,14.975) 117(6.175,14.975) 118(5.525,14.975) 119(4.875,14.975) 120(4.225,14.975) 121(3.575,14.975) 122(2.925,14.975) 123(2.275,14.975) 124(1.625,14.975) 125(0.975,14.975) 126(0.325,14.975) 127(-0.325,14.975) 128(-0.975,14.975) 129(-1.625,14.975) 130(-2.275,14.975) 131(-2.925,14.975) 132(-3.575,14.975) 133(-4.225,14.975) 134(-4.875,14.975) 135(-5.525,14.975) 136(-6.175,14.975) 137(-6.825,14.975) 138(-7.475,14.975) 139(-8.125,14.975) 140(-8.775,14.975) 141(-9.425,14.975) 142(-10.075,14.975) 143(-10.725,14.975) 144(-11.375,14.975)
Top Overlay:
  circle w0.25: c-14.975,12.125 r0.125
  circle w0.6: c-12.65,11.375 r0.3
  lines w0.2: -13.65,-13.65 13.65,-13.65 13.65,13.65 -13.65,13.65 -13.65,-13.65

## QFP28X28-G160/G28N [mm]
pads (160):
  rect 1.9x0.4 smd: 1(-14.95,12.675) 2(-14.95,12.025) 3(-14.95,11.375) 4(-14.95,10.725) 5(-14.95,10.075) 6(-14.95,9.425) 7(-14.95,8.775) 8(-14.95,8.125) 9(-14.95,7.475) 10(-14.95,6.825) 11(-14.95,6.175) 12(-14.95,5.525) 13(-14.95,4.875) 14(-14.95,4.225) 15(-14.95,3.575) 16(-14.95,2.925) 17(-14.95,2.275) 18(-14.95,1.625) 19(-14.95,0.975) 20(-14.95,0.325) 21(-14.95,-0.325) 22(-14.95,-0.975) 23(-14.95,-1.625) 24(-14.95,-2.275) 25(-14.95,-2.925) 26(-14.95,-3.575) 27(-14.95,-4.225) 28(-14.95,-4.875) 29(-14.95,-5.525) 30(-14.95,-6.175) 31(-14.95,-6.825) 32(-14.95,-7.475) 33(-14.95,-8.125) 34(-14.95,-8.775) 35(-14.95,-9.425) 36(-14.95,-10.075) 37(-14.95,-10.725) 38(-14.95,-11.375) 39(-14.95,-12.025) 40(-14.95,-12.675) 81(14.95,-12.675) 82(14.95,-12.025) 83(14.95,-11.375) 84(14.95,-10.725) 85(14.95,-10.075) 86(14.95,-9.425) 87(14.95,-8.775) 88(14.95,-8.125) 89(14.95,-7.475) 90(14.95,-6.825) 91(14.95,-6.175) 92(14.95,-5.525) 93(14.95,-4.875) 94(14.95,-4.225) 95(14.95,-3.575) 96(14.95,-2.925) 97(14.95,-2.275) 98(14.95,-1.625) 99(14.95,-0.975) 100(14.95,-0.325) 101(14.95,0.325) 102(14.95,0.975) 103(14.95,1.625) 104(14.95,2.275) 105(14.95,2.925) 106(14.95,3.575) 107(14.95,4.225) 108(14.95,4.875) 109(14.95,5.525) 110(14.95,6.175) 111(14.95,6.825) 112(14.95,7.475) 113(14.95,8.125) 114(14.95,8.775) 115(14.95,9.425) 116(14.95,10.075) 117(14.95,10.725) 118(14.95,11.375) 119(14.95,12.025) 120(14.95,12.675)
  rect 0.4x1.9 smd: 41(-12.675,-14.95) 42(-12.025,-14.95) 43(-11.375,-14.95) 44(-10.725,-14.95) 45(-10.075,-14.95) 46(-9.425,-14.95) 47(-8.775,-14.95) 48(-8.125,-14.95) 49(-7.475,-14.95) 50(-6.825,-14.95) 51(-6.175,-14.95) 52(-5.525,-14.95) 53(-4.875,-14.95) 54(-4.225,-14.95) 55(-3.575,-14.95) 56(-2.925,-14.95) 57(-2.275,-14.95) 58(-1.625,-14.95) 59(-0.975,-14.95) 60(-0.325,-14.95) 61(0.325,-14.95) 62(0.975,-14.95) 63(1.625,-14.95) 64(2.275,-14.95) 65(2.925,-14.95) 66(3.575,-14.95) 67(4.225,-14.95) 68(4.875,-14.95) 69(5.525,-14.95) 70(6.175,-14.95) 71(6.825,-14.95) 72(7.475,-14.95) 73(8.125,-14.95) 74(8.775,-14.95) 75(9.425,-14.95) 76(10.075,-14.95) 77(10.725,-14.95) 78(11.375,-14.95) 79(12.025,-14.95) 80(12.675,-14.95) 121(12.675,14.95) 122(12.025,14.95) 123(11.375,14.95) 124(10.725,14.95) 125(10.075,14.95) 126(9.425,14.95) 127(8.775,14.95) 128(8.125,14.95) 129(7.475,14.95) 130(6.825,14.95) 131(6.175,14.95) 132(5.525,14.95) 133(4.875,14.95) 134(4.225,14.95) 135(3.575,14.95) 136(2.925,14.95) 137(2.275,14.95) 138(1.625,14.95) 139(0.975,14.95) 140(0.325,14.95) 141(-0.325,14.95) 142(-0.975,14.95) 143(-1.625,14.95) 144(-2.275,14.95) 145(-2.925,14.95) 146(-3.575,14.95) 147(-4.225,14.95) 148(-4.875,14.95) 149(-5.525,14.95) 150(-6.175,14.95) 151(-6.825,14.95) 152(-7.475,14.95) 153(-8.125,14.95) 154(-8.775,14.95) 155(-9.425,14.95) 156(-10.075,14.95) 157(-10.725,14.95) 158(-11.375,14.95) 159(-12.025,14.95) 160(-12.675,14.95)
Top Overlay:
  circle w0.25: c-14.95,13.425 r0.125
  lines w0.2: -13.6,-13.6 13.6,-13.6 13.6,13.6 -13.6,13.6 -13.6,-13.6

## QFP28x28-G160/Y1.4N [mm]
pads (160):
  rect 1.4x0.4 smd: 1(0,0) 2(0,-0.65) 3(0,-1.3) 4(0,-1.95) 5(0,-2.6) 6(0,-3.25) 7(0,-3.9) 8(0,-4.55) 9(0,-5.2) 10(0,-5.85) 11(0,-6.5) 12(0,-7.15) 13(0,-7.8) 14(0,-8.45) 15(0,-9.1) 16(0,-9.75) 17(0,-10.4) 18(0,-11.05) 19(0,-11.7) 20(0,-12.35) 21(0,-13) 22(0,-13.65) 23(0,-14.3) 24(0,-14.95) 25(0,-15.6) 26(0,-16.25) 27(0,-16.9) 28(0,-17.55) 29(0,-18.2) 30(0,-18.85) 31(0,-19.5) 32(0,-20.15) 33(0,-20.8) 34(0,-21.45) 35(0,-22.1) 36(0,-22.75) 37(0,-23.4) 38(0,-24.05) 39(0,-24.7) 40(0,-25.35) 81(31.1,-25.35) 82(31.1,-24.7) 83(31.1,-24.05) 84(31.1,-23.4) 85(31.1,-22.75) 86(31.1,-22.1) 87(31.1,-21.45) 88(31.1,-20.8) 89(31.1,-20.15) 90(31.1,-19.5) 91(31.1,-18.85) 92(31.1,-18.2) 93(31.1,-17.55) 94(31.1,-16.9) 95(31.1,-16.25) 96(31.1,-15.6) 97(31.1,-14.95) 98(31.1,-14.3) 99(31.1,-13.65) 100(31.1,-13) 101(31.1,-12.35) 102(31.1,-11.7) 103(31.1,-11.05) 104(31.1,-10.4) 105(31.1,-9.75) 106(31.1,-9.1) 107(31.1,-8.45) 108(31.1,-7.8) 109(31.1,-7.15) 110(31.1,-6.5) 111(31.1,-5.85) 112(31.1,-5.2) 113(31.1,-4.55) 114(31.1,-3.9) 115(31.1,-3.25) 116(31.1,-2.6) 117(31.1,-1.95) 118(31.1,-1.3) 119(31.1,-0.65) 120(31.1,0)
  rect 0.4x1.4 smd: 41(2.875,-28.225) 42(3.525,-28.225) 43(4.175,-28.225) 44(4.825,-28.225) 45(5.475,-28.225) 46(6.125,-28.225) 47(6.775,-28.225) 48(7.425,-28.225) 49(8.075,-28.225) 50(8.725,-28.225) 51(9.375,-28.225) 52(10.025,-28.225) 53(10.675,-28.225) 54(11.325,-28.225) 55(11.975,-28.225) 56(12.625,-28.225) 57(13.275,-28.225) 58(13.925,-28.225) 59(14.575,-28.225) 60(15.225,-28.225) 61(15.875,-28.225) 62(16.525,-28.225) 63(17.175,-28.225) 64(17.825,-28.225) 65(18.475,-28.225) 66(19.125,-28.225) 67(19.775,-28.225) 68(20.425,-28.225) 69(21.075,-28.225) 70(21.725,-28.225) 71(22.375,-28.225) 72(23.025,-28.225) 73(23.675,-28.225) 74(24.325,-28.225) 75(24.975,-28.225) 76(25.625,-28.225) 77(26.275,-28.225) 78(26.925,-28.225) 79(27.575,-28.225) 80(28.225,-28.225) 121(28.225,2.875) 122(27.575,2.875) 123(26.925,2.875) 124(26.275,2.875) 125(25.625,2.875) 126(24.975,2.875) 127(24.325,2.875) 128(23.675,2.875) 129(23.025,2.875) 130(22.375,2.875) 131(21.725,2.875) 132(21.075,2.875) 133(20.425,2.875) 134(19.775,2.875) 135(19.125,2.875) 136(18.475,2.875) 137(17.825,2.875) 138(17.175,2.875) 139(16.525,2.875) 140(15.875,2.875) 141(15.225,2.875) 142(14.575,2.875) 143(13.925,2.875) 144(13.275,2.875) 145(12.625,2.875) 146(11.975,2.875) 147(11.325,2.875) 148(10.675,2.875) 149(10.025,2.875) 150(9.375,2.875) 151(8.725,2.875) 152(8.075,2.875) 153(7.425,2.875) 154(6.775,2.875) 155(6.125,2.875) 156(5.475,2.875) 157(4.825,2.875) 158(4.175,2.875) 159(3.525,2.875) 160(2.875,2.875)
Top Overlay:
  circle w0.25: c0,0.75 r0.125
  circle w0.6: c2.1,0 r0.3
  lines w0.2: 1.1,-27.125 1.1,1.775 30,1.775 30,-27.125 1.1,-27.125

## QFP28X28-G160/Y1.65N [mm]
pads (160):
  rect 1.65x0.4 smd: 1(-15.075,12.675) 2(-15.075,12.025) 3(-15.075,11.375) 4(-15.075,10.725) 5(-15.075,10.075) 6(-15.075,9.425) 7(-15.075,8.775) 8(-15.075,8.125) 9(-15.075,7.475) 10(-15.075,6.825) 11(-15.075,6.175) 12(-15.075,5.525) 13(-15.075,4.875) 14(-15.075,4.225) 15(-15.075,3.575) 16(-15.075,2.925) 17(-15.075,2.275) 18(-15.075,1.625) 19(-15.075,0.975) 20(-15.075,0.325) 21(-15.075,-0.325) 22(-15.075,-0.975) 23(-15.075,-1.625) 24(-15.075,-2.275) 25(-15.075,-2.925) 26(-15.075,-3.575) 27(-15.075,-4.225) 28(-15.075,-4.875) 29(-15.075,-5.525) 30(-15.075,-6.175) 31(-15.075,-6.825) 32(-15.075,-7.475) 33(-15.075,-8.125) 34(-15.075,-8.775) 35(-15.075,-9.425) 36(-15.075,-10.075) 37(-15.075,-10.725) 38(-15.075,-11.375) 39(-15.075,-12.025) 40(-15.075,-12.675) 81(15.075,-12.675) 82(15.075,-12.025) 83(15.075,-11.375) 84(15.075,-10.725) 85(15.075,-10.075) 86(15.075,-9.425) 87(15.075,-8.775) 88(15.075,-8.125) 89(15.075,-7.475) 90(15.075,-6.825) 91(15.075,-6.175) 92(15.075,-5.525) 93(15.075,-4.875) 94(15.075,-4.225) 95(15.075,-3.575) 96(15.075,-2.925) 97(15.075,-2.275) 98(15.075,-1.625) 99(15.075,-0.975) 100(15.075,-0.325) 101(15.075,0.325) 102(15.075,0.975) 103(15.075,1.625) 104(15.075,2.275) 105(15.075,2.925) 106(15.075,3.575) 107(15.075,4.225) 108(15.075,4.875) 109(15.075,5.525) 110(15.075,6.175) 111(15.075,6.825) 112(15.075,7.475) 113(15.075,8.125) 114(15.075,8.775) 115(15.075,9.425) 116(15.075,10.075) 117(15.075,10.725) 118(15.075,11.375) 119(15.075,12.025) 120(15.075,12.675)
  rect 0.4x1.65 smd: 41(-12.675,-15.075) 42(-12.025,-15.075) 43(-11.375,-15.075) 44(-10.725,-15.075) 45(-10.075,-15.075) 46(-9.425,-15.075) 47(-8.775,-15.075) 48(-8.125,-15.075) 49(-7.475,-15.075) 50(-6.825,-15.075) 51(-6.175,-15.075) 52(-5.525,-15.075) 53(-4.875,-15.075) 54(-4.225,-15.075) 55(-3.575,-15.075) 56(-2.925,-15.075) 57(-2.275,-15.075) 58(-1.625,-15.075) 59(-0.975,-15.075) 60(-0.325,-15.075) 61(0.325,-15.075) 62(0.975,-15.075) 63(1.625,-15.075) 64(2.275,-15.075) 65(2.925,-15.075) 66(3.575,-15.075) 67(4.225,-15.075) 68(4.875,-15.075) 69(5.525,-15.075) 70(6.175,-15.075) 71(6.825,-15.075) 72(7.475,-15.075) 73(8.125,-15.075) 74(8.775,-15.075) 75(9.425,-15.075) 76(10.075,-15.075) 77(10.725,-15.075) 78(11.375,-15.075) 79(12.025,-15.075) 80(12.675,-15.075) 121(12.675,15.075) 122(12.025,15.075) 123(11.375,15.075) 124(10.725,15.075) 125(10.075,15.075) 126(9.425,15.075) 127(8.775,15.075) 128(8.125,15.075) 129(7.475,15.075) 130(6.825,15.075) 131(6.175,15.075) 132(5.525,15.075) 133(4.875,15.075) 134(4.225,15.075) 135(3.575,15.075) 136(2.925,15.075) 137(2.275,15.075) 138(1.625,15.075) 139(0.975,15.075) 140(0.325,15.075) 141(-0.325,15.075) 142(-0.975,15.075) 143(-1.625,15.075) 144(-2.275,15.075) 145(-2.925,15.075) 146(-3.575,15.075) 147(-4.225,15.075) 148(-4.875,15.075) 149(-5.525,15.075) 150(-6.175,15.075) 151(-6.825,15.075) 152(-7.475,15.075) 153(-8.125,15.075) 154(-8.775,15.075) 155(-9.425,15.075) 156(-10.075,15.075) 157(-10.725,15.075) 158(-11.375,15.075) 159(-12.025,15.075) 160(-12.675,15.075)
Top Overlay:
  circle w0.25: c-15.075,13.425 r0.125
  circle w0.6: c-12.85,12.675 r0.3
  lines w0.2: -13.85,-13.85 13.85,-13.85 13.85,13.85 -13.85,13.85 -13.85,-13.85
